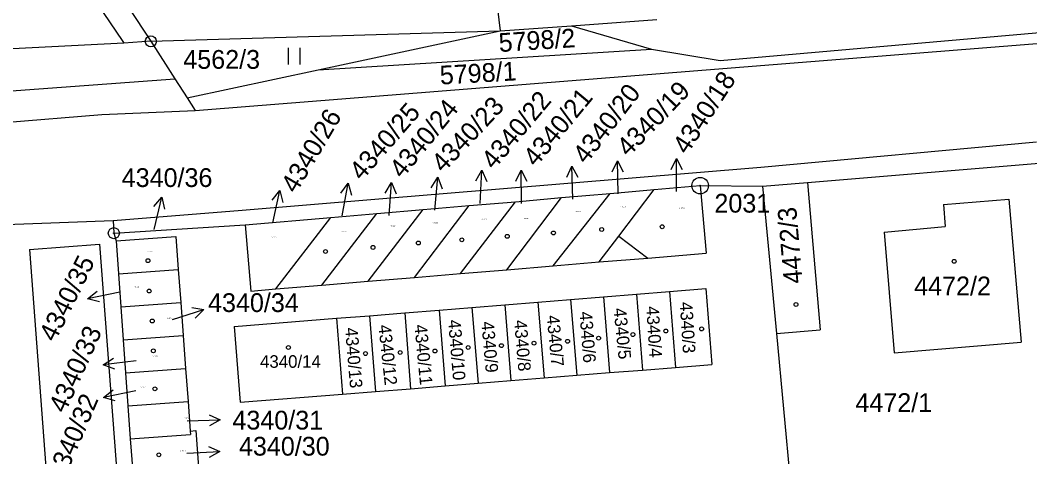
# Model space of a CAD drawing. Extents: x -735092 to -733385, y -1122435 to -1118992.
# Drawn here: x -734384.1 to -734292.6, y -1119776.3 to -1119736.8 of the extents above; entities that cross this region are included whole.
import ezdxf

# ---------------------------------------------------------------- set-up
doc = ezdxf.new("R2010")
doc.units = 0
for name, color, linetype in [('Vrstva 1', 7, 'Continuous'), ('Vrstva 16', 7, 'Continuous'), ('Vrstva 17', 7, 'Continuous'), ('Vrstva 18', 7, 'Continuous'), ('Vrstva 19', 7, 'Continuous'), ('Vrstva 25', 7, 'Continuous'), ('Vrstva 4', 7, 'Continuous')]:
    doc.layers.add(name, color=color, linetype=linetype)

msp = doc.modelspace()

# ---------------------------------------------------------------- linework, layer by layer
at = {"layer": 'Vrstva 1'}
for points in [[(-734436.6, -1119647.62), (-734429.17, -1119658.57), (-734374.77, -1119738.74), (-734374.66, -1119738.9)], [(-734349.09, -1119667.54), (-734340.6, -1119737.77)], [(-734419.19, -1119667.95), (-734372.23, -1119738.72)], [(-734368.21, -1119745), (-734266.19, -1119736.86)], [(-734334.12, -1119737.31), (-734326.41, -1119736.76)], [(-734320.66, -1119740.46), (-734279.66, -1119736.88)], [(-734372.23, -1119738.72), (-734340.6, -1119737.77)], [(-734357.08, -1119741.31), (-734340.6, -1119737.77)], [(-734340.6, -1119737.77), (-734334.12, -1119737.31)], [(-734334.12, -1119737.31), (-734326.88, -1119739.42)], [(-734374.66, -1119738.9), (-734436.95, -1119742.07)], [(-734372.23, -1119738.72), (-734374.66, -1119738.9)], [(-734372.23, -1119738.72), (-734370.05, -1119742.13)], [(-734357.08, -1119741.31), (-734326.88, -1119739.42)], [(-734326.88, -1119739.42), (-734320.66, -1119740.46)], [(-734368.95, -1119743.85), (-734357.08, -1119741.31)], [(-734435.78, -1119746.95), (-734370.05, -1119742.13)], [(-734370.05, -1119742.13), (-734368.95, -1119743.85)], [(-734368.95, -1119743.85), (-734368.21, -1119745)], [(-734412.09, -1119748.24), (-734376.67, -1119745.36)], [(-734376.67, -1119745.36), (-734368.21, -1119745)], [(-734317, -1119750.12), (-734292.01, -1119747.82)], [(-734312.77, -1119751.49), (-734291.79, -1119749.76)], [(-734363.95, -1119754.01), (-734317, -1119750.12)], [(-734326.66, -1119752.15), (-734322.48, -1119751.79)], [(-734322.48, -1119751.79), (-734321.95, -1119757.9)], [(-734322.48, -1119751.79), (-734316.83, -1119751.83)], [(-734316.83, -1119751.83), (-734312.77, -1119751.49)], [(-734316.83, -1119751.83), (-734315.57, -1119765.17)], [(-734312.77, -1119751.49), (-734311.61, -1119764.83)], [(-734335.8, -1119759.05), (-734330.64, -1119752.5)], [(-734335.03, -1119752.87), (-734330.64, -1119752.5)], [(-734330.64, -1119752.5), (-734326.66, -1119752.15)], [(-734329.86, -1119756.37), (-734326.66, -1119752.15)], [(-734348.36, -1119760.1), (-734343.39, -1119753.6)], [(-734347.57, -1119753.96), (-734343.39, -1119753.6)], [(-734344.17, -1119759.75), (-734339.21, -1119753.24)], [(-734343.39, -1119753.6), (-734339.21, -1119753.24)], [(-734339.99, -1119759.4), (-734335.03, -1119752.87)], [(-734339.21, -1119753.24), (-734335.03, -1119752.87)], [(-734300.45, -1119753.51), (-734294.52, -1119753)], [(-734300.45, -1119753.51), (-734300.28, -1119755.5)], [(-734294.52, -1119753), (-734293.42, -1119765.97)], [(-734375.63, -1119754.93), (-734363.95, -1119754.01)], [(-734356.73, -1119760.79), (-734351.75, -1119754.32)], [(-734355.93, -1119754.68), (-734351.75, -1119754.32)], [(-734352.55, -1119760.45), (-734347.57, -1119753.96)], [(-734351.75, -1119754.32), (-734347.57, -1119753.96)], [(-734400.74, -1119755.88), (-734375.63, -1119754.93)], [(-734375.63, -1119754.93), (-734375.58, -1119756.09)], [(-734375.58, -1119756.09), (-734363.68, -1119755.35)], [(-734363.68, -1119755.35), (-734355.93, -1119754.68)], [(-734363.68, -1119755.35), (-734363.16, -1119761.33)], [(-734360.92, -1119761.14), (-734355.93, -1119754.68)], [(-734305.83, -1119755.99), (-734300.28, -1119755.5)], [(-734375.58, -1119756.09), (-734375.37, -1119756.79)], [(-734375.37, -1119756.79), (-734369.96, -1119756.4)], [(-734369.96, -1119756.4), (-734369.74, -1119759.39)], [(-734331.62, -1119758.7), (-734329.86, -1119756.37)], [(-734305.83, -1119755.99), (-734304.9, -1119766.92)], [(-734383.21, -1119757.57), (-734376.87, -1119757.09)], [(-734376.87, -1119757.09), (-734371.31, -1119830.28)], [(-734375.37, -1119756.79), (-734375.16, -1119759.78)], [(-734383.21, -1119757.57), (-734380.73, -1119790.54)], [(-734327.23, -1119758.34), (-734321.95, -1119757.9)], [(-734339.99, -1119759.4), (-734335.8, -1119759.05)], [(-734335.8, -1119759.05), (-734331.62, -1119758.7)], [(-734331.62, -1119758.7), (-734327.23, -1119758.34)], [(-734375.16, -1119759.78), (-734369.74, -1119759.39)], [(-734375.16, -1119759.78), (-734374.94, -1119762.77)], [(-734369.74, -1119759.39), (-734369.52, -1119762.38)], [(-734352.55, -1119760.45), (-734348.36, -1119760.1)], [(-734348.36, -1119760.1), (-734344.17, -1119759.75)], [(-734344.17, -1119759.75), (-734339.99, -1119759.4)], [(-734360.92, -1119761.14), (-734356.73, -1119760.79)], [(-734356.73, -1119760.79), (-734352.55, -1119760.45)], [(-734363.16, -1119761.33), (-734360.92, -1119761.14)], [(-734334.21, -1119762.1), (-734331.24, -1119761.86)], [(-734331.24, -1119761.86), (-734328.24, -1119761.62)], [(-734331.24, -1119761.86), (-734330.68, -1119768.72)], [(-734328.24, -1119761.62), (-734325.25, -1119761.38)], [(-734328.24, -1119761.62), (-734327.69, -1119768.48)], [(-734325.25, -1119761.38), (-734321.97, -1119761.11)], [(-734325.25, -1119761.38), (-734324.7, -1119768.24)], [(-734321.97, -1119761.11), (-734321.42, -1119767.97)], [(-734374.94, -1119762.77), (-734369.52, -1119762.38)], [(-734374.94, -1119762.77), (-734374.73, -1119765.76)], [(-734369.52, -1119762.38), (-734369.3, -1119765.36)], [(-734346.13, -1119763.06), (-734343.15, -1119762.82)], [(-734343.15, -1119762.82), (-734340.17, -1119762.58)], [(-734343.15, -1119762.82), (-734342.59, -1119769.67)], [(-734340.17, -1119762.58), (-734337.17, -1119762.34)], [(-734340.17, -1119762.58), (-734339.62, -1119769.44)], [(-734337.17, -1119762.34), (-734334.21, -1119762.1)], [(-734337.17, -1119762.34), (-734336.61, -1119769.19)], [(-734334.21, -1119762.1), (-734333.65, -1119768.96)], [(-734355.41, -1119763.8), (-734352.43, -1119763.56)], [(-734352.43, -1119763.56), (-734349.23, -1119763.31)], [(-734352.43, -1119763.56), (-734351.87, -1119770.42)], [(-734349.23, -1119763.31), (-734346.13, -1119763.06)], [(-734349.23, -1119763.31), (-734348.72, -1119770.17)], [(-734346.13, -1119763.06), (-734345.58, -1119769.91)], [(-734364.68, -1119764.55), (-734355.41, -1119763.8)], [(-734364.68, -1119764.55), (-734364.13, -1119771.4)], [(-734355.41, -1119763.8), (-734354.86, -1119770.66)], [(-734374.73, -1119765.76), (-734369.3, -1119765.36)], [(-734369.3, -1119765.36), (-734369.08, -1119768.35)], [(-734315.57, -1119765.17), (-734311.61, -1119764.83)], [(-734315.57, -1119765.17), (-734314.29, -1119778.81)], [(-734374.73, -1119765.76), (-734374.51, -1119768.74)], [(-734304.9, -1119766.92), (-734293.42, -1119765.97)], [(-734327.69, -1119768.48), (-734324.7, -1119768.24)], [(-734324.7, -1119768.24), (-734321.42, -1119767.97)], [(-734374.51, -1119768.74), (-734369.08, -1119768.35)], [(-734374.51, -1119768.74), (-734374.3, -1119771.73)], [(-734369.08, -1119768.35), (-734368.86, -1119771.34)], [(-734339.62, -1119769.44), (-734336.61, -1119769.19)], [(-734336.61, -1119769.19), (-734333.65, -1119768.96)], [(-734333.65, -1119768.96), (-734330.68, -1119768.72)], [(-734330.68, -1119768.72), (-734327.69, -1119768.48)], [(-734351.87, -1119770.42), (-734348.72, -1119770.17)], [(-734348.72, -1119770.17), (-734345.58, -1119769.91)], [(-734345.58, -1119769.91), (-734342.59, -1119769.67)], [(-734342.59, -1119769.67), (-734339.62, -1119769.44)], [(-734364.13, -1119771.4), (-734354.86, -1119770.66)], [(-734354.86, -1119770.66), (-734351.87, -1119770.42)], [(-734374.3, -1119771.73), (-734368.86, -1119771.34)], [(-734374.3, -1119771.73), (-734374.09, -1119774.72)], [(-734368.86, -1119771.34), (-734368.66, -1119774.01)], [(-734374.09, -1119774.72), (-734368.64, -1119774.33)], [(-734374.09, -1119774.72), (-734373.87, -1119777.71)], [(-734368.66, -1119774.01), (-734368.16, -1119773.97)], [(-734368.66, -1119774.01), (-734368.64, -1119774.33)], [(-734368.16, -1119773.97), (-734367.92, -1119777.28)]]:
    msp.add_lwpolyline(points, dxfattribs=at)
at = {"layer": 'Vrstva 25'}
for points in [[(-734359.747, -1119740.815), (-734359.747, -1119739.315)], [(-734358.713, -1119740.815), (-734358.713, -1119739.315)], [(-734334.559, -1119751.036), (-734334.088, -1119750.022), (-734333.56, -1119751.007)], [(-734334, -1119753.02), (-734334.088, -1119750.022)], [(-734330.455, -1119750.552), (-734329.978, -1119749.541), (-734329.456, -1119750.53)], [(-734329.91, -1119752.54), (-734329.978, -1119749.541)], [(-734325.11, -1119750.33), (-734324.61, -1119749.33), (-734324.11, -1119750.33)], [(-734324.61, -1119752.33), (-734324.61, -1119749.33)], [(-734342.808, -1119751.368), (-734342.259, -1119750.394), (-734341.81, -1119751.418)], [(-734342.41, -1119753.39), (-734342.259, -1119750.394)], [(-734339.184, -1119751.397), (-734338.696, -1119750.391), (-734338.185, -1119751.385)], [(-734338.66, -1119753.39), (-734338.696, -1119750.391)], [(-734355.026, -1119752.462), (-734354.348, -1119751.574), (-734354.045, -1119752.65)], [(-734354.91, -1119754.52), (-734354.348, -1119751.574)], [(-734351.002, -1119752.469), (-734350.431, -1119751.509), (-734350.005, -1119752.542)], [(-734350.65, -1119754.5), (-734350.431, -1119751.509)], [(-734346.833, -1119751.983), (-734346.243, -1119751.033), (-734345.838, -1119752.075)], [(-734346.52, -1119754.02), (-734346.243, -1119751.033)], [(-734361.253, -1119753.1), (-734360.557, -1119752.226), (-734360.276, -1119753.308)], [(-734361.18, -1119755.16), (-734360.557, -1119752.226)], [(-734371.948, -1119753.689), (-734371.225, -1119752.837), (-734370.978, -1119753.927)], [(-734371.94, -1119755.75), (-734371.225, -1119752.837)], [(-734376.885, -1119762.318), (-734377.966, -1119762.033), (-734377.089, -1119761.34)], [(-734375.03, -1119761.42), (-734377.966, -1119762.033)], [(-734368.518, -1119762.831), (-734367.415, -1119763.013), (-734368.222, -1119763.787)], [(-734370.28, -1119763.9), (-734367.415, -1119763.013)], [(-734375.494, -1119768.4), (-734376.547, -1119768.025), (-734375.616, -1119767.408)], [(-734373.57, -1119767.66), (-734376.547, -1119768.025)], [(-734375.447, -1119771.265), (-734376.527, -1119770.978), (-734375.649, -1119770.286)], [(-734373.59, -1119770.37), (-734376.527, -1119770.978)], [(-734366.952, -1119772.525), (-734365.941, -1119773.002), (-734366.93, -1119773.524)], [(-734368.94, -1119773.07), (-734365.941, -1119773.002)], [(-734367.007, -1119775.413), (-734365.984, -1119775.864), (-734366.958, -1119776.411)], [(-734368.98, -1119776.01), (-734365.984, -1119775.864)]]:
    msp.add_lwpolyline(points, dxfattribs=at)
for centre, radius in [((-734372.23, -1119738.72), 0.5), ((-734372.23, -1119738.72), 0.032), ((-734322.48, -1119751.79), 0.75), ((-734322.48, -1119751.79), 0.032), ((-734325.92, -1119755.51), 0.175), ((-734375.58, -1119756.09), 0.5), ((-734375.58, -1119756.09), 0.032), ((-734339.95, -1119756.38), 0.175), ((-734335.77, -1119756.07), 0.175), ((-734331.4, -1119755.76), 0.175), ((-734352.11, -1119757.38), 0.175), ((-734348, -1119756.98), 0.175), ((-734344.06, -1119756.69), 0.175), ((-734356.41, -1119757.75), 0.175), ((-734372.49, -1119758.58), 0.175), ((-734299.48, -1119758.64), 0.175), ((-734372.38, -1119761.33), 0.175), ((-734313.8, -1119762.55), 0.175), ((-734372.1, -1119764.04), 0.175), ((-734322.35, -1119764.76), 0.175), ((-734331.68, -1119765.6), 0.175), ((-734328.57, -1119765.27), 0.175), ((-734325.59, -1119764.95), 0.175), ((-734359.77, -1119766.44), 0.175), ((-734343.49, -1119766.44), 0.175), ((-734340.48, -1119766.27), 0.175), ((-734337.53, -1119766.05), 0.175), ((-734334.49, -1119765.88), 0.175), ((-734372, -1119766.74), 0.175), ((-734352.79, -1119766.99), 0.175), ((-734349.65, -1119766.89), 0.175), ((-734346.5, -1119766.76), 0.175), ((-734371.86, -1119770.18), 0.175), ((-734371.5, -1119776.16), 0.175)]:
    msp.add_circle(centre, radius, dxfattribs=at)
at = {"layer": 'Vrstva 4'}
msp.add_lwpolyline([(-734329.86, -1119756.37), (-734327.23, -1119758.34)], dxfattribs=at)

# ---------------------------------------------------------------- texts
at = {"layer": 'Vrstva 16'}
for s, rotation, p in [('4340/18', 56.90045, (-734323.668, -1119749.054)), ('4340/20', 52.30042, (-734332.815, -1119749.92)), ('4340/19', 46.00037, (-734328.984, -1119749.258)), ('4340/22', 49.9004, (-734341.154, -1119750.419)), ('4340/21', 50.3004, (-734337.356, -1119750.169)), ('4340/25', 48.90039, (-734353.129, -1119751.418)), ('4340/24', 50.8004, (-734349.458, -1119751.229)), ('4340/23', 46.70037, (-734345.748, -1119750.694)), ('4340/26', 59.30047, (-734359.089, -1119752.576)), ('4340/35', 63.60051, (-734380.91, -1119766.026)), ('4340/33', 65.70052, (-734379.999, -1119772.478)), ('4340/32', 66.80053, (-734380.17, -1119778.663))]:
    msp.add_text(s, height=1.7, rotation=rotation, dxfattribs=at).set_placement(p)
for s, p in [('4340/36', (-734374.868, -1119751.91)), ('4340/34', (-734367.048, -1119763.23)), ('4340/31', (-734364.84, -1119773.87)), ('4340/30', (-734364.248, -1119776.23))]:
    msp.add_text(s, height=1.7, dxfattribs=at).set_placement(p)
at = {"layer": 'Vrstva 17'}
msp.add_text('2031', height=1.7, dxfattribs=at).set_placement((-734321.19, -1119754.23))
at = {"layer": 'Vrstva 18'}
for s, rotation, p in [('5798/2', 3.70003, (-734340.674, -1119739.698)), ('5798/1', 3.20003, (-734346.012, -1119742.64))]:
    msp.add_text(s, height=1.7, rotation=rotation, dxfattribs=at).set_placement(p)
for s, height, p in [('4562/3', 1.7, (-734369.29, -1119741.21)), ('4340/26', 0.1, (-734361.31, -1119756.5)), ('4472/1', 1.7, (-734308.42, -1119772.28)), ('4340/31', 0.1, (-734369.21, -1119772.88))]:
    msp.add_text(s, height=height, dxfattribs=at).set_placement(p)
at = {"layer": 'Vrstva 19'}
for s, height, p in [('4340/19', 0.1, (-734329.68, -1119753.75)), ('4340/20', 0.1, (-734333.76, -1119754.18)), ('4340/18', 0.1, (-734324.41, -1119753.87)), ('4340/24', 0.1, (-734350.54, -1119755.49)), ('4340/23', 0.1, (-734346.701, -1119755.19)), ('4340/22', 0.1, (-734342.3, -1119754.87)), ('4340/21', 0.1, (-734338.44, -1119754.81)), ('4340/25', 0.1, (-734355.03, -1119755.99)), ('4340/36', 0.1, (-734372.541, -1119757.8)), ('4472/2', 1.7, (-734303.1, -1119761.72)), ('4340/35', 0.1, (-734373.75, -1119760.99)), ('4340/34', 0.1, (-734370.781, -1119763.84)), ('4340/33', 0.1, (-734372.081, -1119767.27)), ('4340/14', 1.14, (-734362.34, -1119768.28)), ('4340/32', 0.1, (-734373.171, -1119770.08)), ('4340/30', 0.1, (-734369.601, -1119775.84))]:
    msp.add_text(s, height=height, dxfattribs=at).set_placement(p)
for s, height, rotation, p in [('4472/3', 1.7, 94.90076, (-734313.196, -1119760.598)), ('4340/4', 1.14, 273.70218, (-734327.368, -1119762.736)), ('4340/3', 1.14, 273.60217, (-734324.328, -1119762.347)), ('4340/7', 1.14, 275.40219, (-734336.383, -1119763.57)), ('4340/6', 1.14, 274.50218, (-734333.415, -1119763.223)), ('4340/5', 1.14, 275.90219, (-734330.331, -1119762.918)), ('4340/13', 1.14, 274.80219, (-734354.644, -1119764.672)), ('4340/12', 1.14, 276.2022, (-734351.63, -1119764.437)), ('4340/11', 1.14, 275.40219, (-734348.363, -1119764.41)), ('4340/10', 1.14, 274.80219, (-734345.314, -1119763.962)), ('4340/9', 1.14, 275.10219, (-734342.304, -1119764.121)), ('4340/8', 1.14, 274.90219, (-734339.334, -1119763.992))]:
    msp.add_text(s, height=height, rotation=rotation, dxfattribs=at).set_placement(p)

doc.saveas('drawing.dxf')
